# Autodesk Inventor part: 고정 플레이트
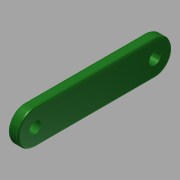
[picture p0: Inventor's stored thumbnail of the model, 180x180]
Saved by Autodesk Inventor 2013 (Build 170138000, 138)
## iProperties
Created: 2017-04
Part Number: 고정 플레이트
Material: 스테인리스강
Document SubType Name: Modeling
Designer: mduedu
Density: 8.08 g/cm^3
Mass: 9.86033 g
Surface Area: 11.4535 cm^2
Volume: 1.22034 cm^3
Author: mduedu
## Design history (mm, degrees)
sketch "스케치1"
  geometry: L1 (0, 17.5)-(0, -17.5); L2 (-5, 17.5)-(-5, -17.5); L3 (5, -17.5)-(5, 17.5); A1 r 5 centre (0, 17.5) between (5, 17.5) and (-5, 17.5); A2 r 5 centre (0, -17.5) between (-5, -17.5) and (5, -17.5); 2 further points
  constraints: 6 end point, 4 point on circle, 4 tangent, 3 coincident, 2 centre point, 1 midpoint, 1 parallel, 1 vertical
  dimensions: "d0" = 35 distance of L1.start L1.end; "d1" = 5 radius of A2
extrude "돌출1" new body sketch "스케치1" distance "d2" = 3; taper "d3" = 0 deg
fillet "모깎기1" dims "d4" = 0.5
sketch "스케치2"
  geometry: A1 r 5 centre (-17.5, 0) between (-17.5, 5) and (-17.5, -5) reference; A2 r 5 centre (17.5, 0) between (17.5, -5) and (17.5, 5) reference; 3 further points
  constraints: 2 coincident
sketch "스케치3"
  geometry: 3 further points
  constraints: 3 other
hole "구멍1" sketch "스케치3" at (-17.5, 0), (17.5, 0) diameter "d5" = 3.4; stored, may be unused: countersink angle "d9" = 90 deg, drill point angle "d11" = 0 deg; dims "d6" = 6, "d7" = 4, "d8" = 2, "d10" = 8
node "솔리드1"
